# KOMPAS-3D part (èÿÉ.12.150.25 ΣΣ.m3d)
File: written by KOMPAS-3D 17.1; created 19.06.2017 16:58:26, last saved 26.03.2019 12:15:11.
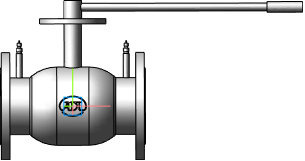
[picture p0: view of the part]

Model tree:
1. Операция без истории:2  (labels: Сталь 20  ГОСТ 1050-88)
